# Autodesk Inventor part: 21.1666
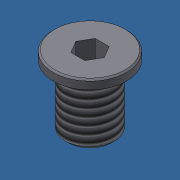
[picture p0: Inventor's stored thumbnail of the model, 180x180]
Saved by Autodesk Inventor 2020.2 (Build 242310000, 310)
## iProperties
Created: 2009-05
Part Number: 21.1666
Material: Stainless Steel
Document SubType Name: Modeling
Designer: Administrator
Mass: 4.75031 g
Surface Area: 5.96938 cm^2
Volume: 0.58791 cm^3
Density: 8.08 g/cm^3
Description: M8x10 Stainless Extra Low Head
Vendor: S
Appearance: Steel
Author: Administrator
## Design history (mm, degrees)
sketch "Sketch1"
  geometry: C1 r 6 at (0, 0); 1 further point
  constraints: 1 centre point, 1 coincident
  dimensions: "d0" = 12 diameter of C1
extrude "Extrusion1" new body sketch "Sketch1" distance "d1" = 1.5; taper "d2" = 0 deg
sketch "Sketch2"
  geometry: C1 r 6 at (0, 0) reference; C2 r 4 at (0, 0)
  constraints: 1 centre point, 1 coincident
  dimensions: "d3" = 8 diameter of C2
extrude "Extrusion2" join sketch "Sketch2" distance "d4" = 10; taper "d5" = 0 deg
thread "Thread1" dims "d6" = 23, "d7" = 0
sketch "Sketch3"
  geometry: L1 (-1.155, 2)-(1.155, 2); L2 (1.155, 2)-(2.309, 0); L3 (2.309, 0)-(1.155, -2); L4 (1.155, -2)-(-1.155, -2); L5 (-1.155, -2)-(-2.309, 0); L6 (-2.309, 0)-(-1.155, 2); C1 r 6 at (0, 0) reference; 1 further point
  constraints: 12 end point, 3 parallel, 2 equal length, 2 horizontal alignment, 1 horizontal, 1 midpoint, 1 vertical alignment
  dimensions: "d8" = 120 deg angle of L2 L1; "d9" = 120 deg angle of L3 L2; "d10" = 4 distance between parallel lines of L3 L6
extrude "Extrusion3" cut sketch "Sketch3" distance "d11" = 5; taper "d12" = 0 deg
sketch "Sketch4"
  geometry: L1 (0, -5)-(2, -5) reference; L2 (2, -5)-(0, -5); L3 (0, -6.5)-(0.5, -6.5); L4 (0, -5)-(0, -6.5); L5 (0.915, -6.368)-(0.085, -6.632); A1 r 2.131 centre (-0.146, -4.47) between (0.164, -6.578) and (0.819, -6.369); 1 further point
  constraints: 8 end point, 2 midpoint, 1 centre point, 1 collinear, 1 parallel, 1 perpendicular, 1 point on circle, 4 other
  dimensions: "d13" = 1.5 distance of L1.start L3.start; "d14" = 0.5 distance of L3.start L3.end
revolve "Revolution1" sketch "Sketch4" stored, may be unused: angle "d15" = 90 deg
chamfer "Chamfer1" distance "d16" = 0.25; stored, may be unused: second distance "d17" = 2, angle "d18" = 45 deg
chamfer "Chamfer2" distance "d19" = 0.5; stored, may be unused: second distance "d20" = 2, angle "d21" = 45 deg
body "Solid1"
